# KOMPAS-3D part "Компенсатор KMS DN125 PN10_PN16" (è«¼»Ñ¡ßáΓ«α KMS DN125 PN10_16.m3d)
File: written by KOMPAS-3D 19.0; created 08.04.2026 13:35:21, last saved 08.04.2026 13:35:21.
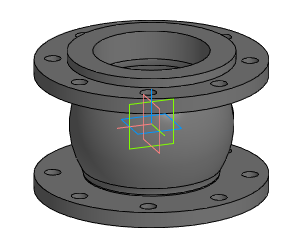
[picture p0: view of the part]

Document properties: Автор: Энергия; Полное имя файла: Z:\3.Личные\kachalov\3d для проектировщиков\7.1 Компенсатор\stp_Компенсатор KSM\Компенсатор KMS DN125 PN10_16.m3d

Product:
- Part/product: Компенсатор KMS DN125 PN10_PN16

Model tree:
1. Операция без истории:1  (labels: Компенсатор KMS DN125 PN10_PN16)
